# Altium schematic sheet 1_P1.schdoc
size 309 x 223 mm; Symbol: Sheet-Symbol_A4; Device: Sheet-Symbol_A4; @Project Name: Macro Pad; @Page Count: 1; @Update Date: 2024-09-08; @Create Date: 2024-01-24; @Schematic Name: Schematic1; @Page No: 1; @Page Name: P1; Company: t; Reviewed: EasyEDA; Version: V0.2; Page Size: A4; Part Number: JLCPCB-002; Drawn: Tiebe Groosman; @Board Name: Board1; @Create Time: 15:44:45; @Update Time: 14:38:24
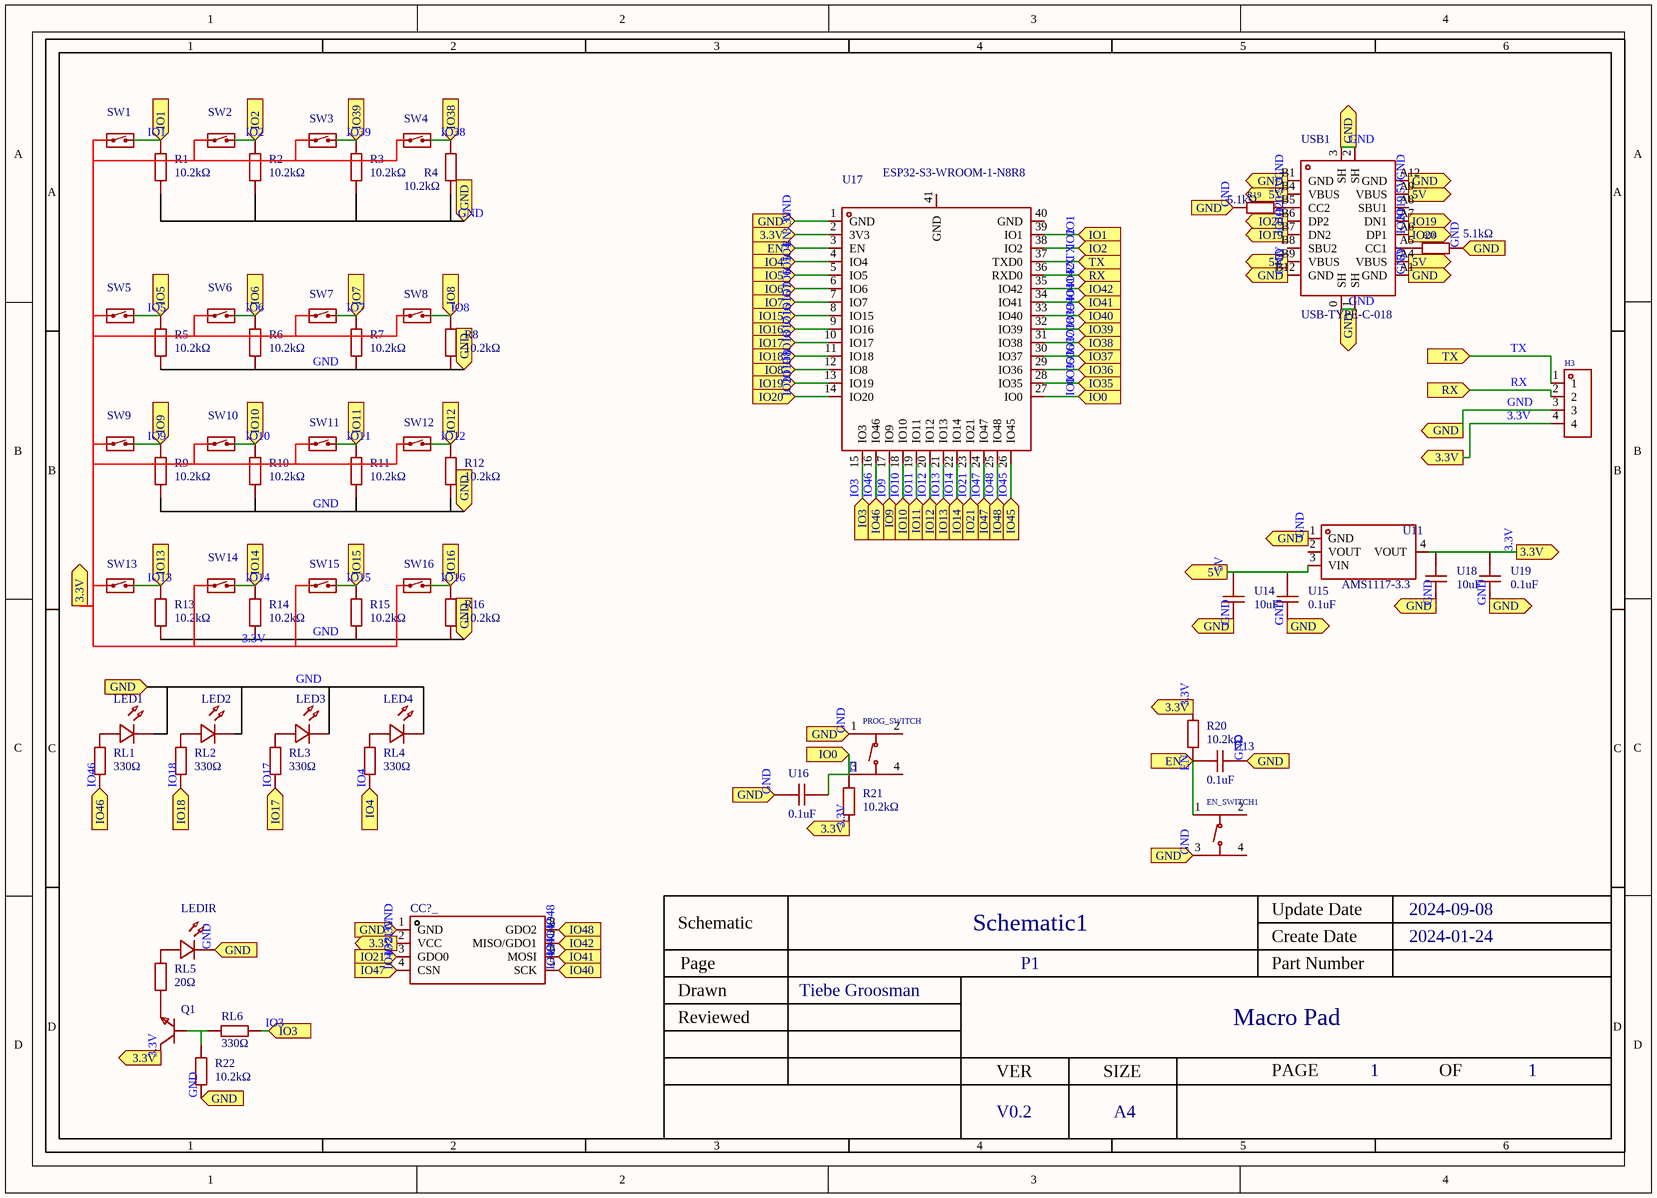
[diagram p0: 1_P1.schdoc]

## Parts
CC?_  CC1101 Module  [CC1101-BOARS]  (value not drawn)
EN_SWITCH1  TS-1187A-B-A-B  [SW-SMD_4P-L5.1-W5.1-P3.70-LS6.5-TL-2]  (value not drawn)
H3  HDR-M_2.54_1x4P  [HDR-TH_4P-P2.54-V-M]  (value not drawn)
LED1  LED_TH-R_5mm  [LED-TH_BD5.8-P2.54-FD]  (value not drawn)
LED2  LED_TH-R_5mm  [LED-TH_BD5.8-P2.54-FD]  (value not drawn)
LED3  LED_TH-R_5mm  [LED-TH_BD5.8-P2.54-FD]  (value not drawn)
LED4  LED_TH-R_5mm  [LED-TH_BD5.8-P2.54-FD]  (value not drawn)
LEDIR  LED_TH-R_5mm  [LED-TH_BD5.8-P2.54-FD]  (value not drawn)
PROG_SWITCH  TS-1187A-B-A-B  [SW-SMD_4P-L5.1-W5.1-P3.70-LS6.5-TL-2]  (value not drawn)
Q1  S8050_NPN  [SOT-23_L2.9-W1.3-P1.90-LS2.4-BR]  (value not drawn)
R1  10.2kΩ  [R1210]  (value not drawn)
R2  10.2kΩ  [R1210]  (value not drawn)
R3  10.2kΩ  [R1210]  (value not drawn)
R4  10.2kΩ  [R1210]  (value not drawn)
R5  10.2kΩ  [R1210]  (value not drawn)
R6  10.2kΩ  [R1210]  (value not drawn)
R7  10.2kΩ  [R1210]  (value not drawn)
R8  10.2kΩ  [R1210]  (value not drawn)
R9  10.2kΩ  [R1210]  (value not drawn)
R10  10.2kΩ  [R1210]  (value not drawn)
R11  10.2kΩ  [R1210]  (value not drawn)
R12  10.2kΩ  [R1210]  (value not drawn)
R13  10.2kΩ  [R1210]  (value not drawn)
R14  10.2kΩ  [R1210]  (value not drawn)
R15  10.2kΩ  [R1210]  (value not drawn)
R16  10.2kΩ  [R1210]  (value not drawn)
R18  5.1kΩ  [R1210]  (value not drawn)
R19  5.1kΩ  [R1210]  (value not drawn)
R20  10.2kΩ  [R1210]  (value not drawn)
R21  10.2kΩ  [R1210]  (value not drawn)
R22  10.2kΩ  [R1210]  (value not drawn)
RL1  330Ω  [R1210]  (value not drawn)
RL2  330Ω  [R1210]  (value not drawn)
RL3  330Ω  [R1210]  (value not drawn)
RL4  330Ω  [R1210]  (value not drawn)
RL5  20Ω  [R1210]  (value not drawn)
RL6  330Ω  [R1210]  (value not drawn)
SW1  CHERRY-MX-LED  [CHERRYMX]  (value not drawn)
SW2  CHERRY-MX-LED  [CHERRYMX]  (value not drawn)
SW3  CHERRY-MX-LED  [CHERRYMX]  (value not drawn)
SW4  CHERRY-MX-LED  [CHERRYMX]  (value not drawn)
SW5  CHERRY-MX-LED  [CHERRYMX]  (value not drawn)
SW6  CHERRY-MX-LED  [CHERRYMX]  (value not drawn)
SW7  CHERRY-MX-LED  [CHERRYMX]  (value not drawn)
SW8  CHERRY-MX-LED  [CHERRYMX]  (value not drawn)
SW9  CHERRY-MX-LED  [CHERRYMX]  (value not drawn)
SW10  CHERRY-MX-LED  [CHERRYMX]  (value not drawn)
SW11  CHERRY-MX-LED  [CHERRYMX]  (value not drawn)
SW12  CHERRY-MX-LED  [CHERRYMX]  (value not drawn)
SW13  CHERRY-MX-LED  [CHERRYMX]  (value not drawn)
SW14  CHERRY-MX-LED  [CHERRYMX]  (value not drawn)
SW15  CHERRY-MX-LED  [CHERRYMX]  (value not drawn)
SW16  CHERRY-MX-LED  [CHERRYMX]  (value not drawn)
U11  AMS1117-3.3  [SOT-223-3_L6.5-W3.4-P2.30-LS7.0-BR]  (value not drawn)
U13  0.1uF  [C1210]  (value not drawn)
U14  10uF  [C1210]  (value not drawn)
U15  0.1uF  [C1210]  (value not drawn)
U16  0.1uF  [C1210]  (value not drawn)
U17  ESP32-S3-WROOM-1-N8R8  [WIRELM-SMD_ESP32-S3-WROOM-1]  (value not drawn)
U18  10uF  [C1210]  (value not drawn)
U19  0.1uF  [C1210]  (value not drawn)
USB1  USB-TYPE-C-018  [USB-C_SMD-TYPE-C-31-M-12]  (value not drawn)

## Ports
3.3V (in), 3.3V (out), 5V (out), EN (in), GND (in), GND (out), IO0 (in), IO1 (in), IO2 (in), IO3 (in), IO4 (in), IO5 (in), IO6 (in), IO7 (in), IO8 (in), IO9 (in), IO10 (in), IO11 (in), IO12 (in), IO13 (in), IO14 (in), IO15 (in), IO16 (in), IO17 (in), IO18 (in), IO19 (in), IO19 (out), IO20 (in), IO20 (out), IO21 (in), IO35 (in), IO36 (in), IO37 (in), IO38 (in), IO39 (in), IO40 (in), IO41 (in), IO42 (in), IO45 (in), IO46 (in), IO47 (in), IO48 (in), RX (in), TX (in)

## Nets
3.3V: CC?_.2(VCC) H3.4 Q1.3(C) R20.2 R21.1 SW1.1 SW2.1 SW3.1 SW4.1 SW5.1 SW6.1 SW7.1 SW8.1 SW9.1 SW10.1 SW11.1 SW12.1 SW13.1 SW14.1 SW15.1 SW16.1 U11.4(VOUT) U17.2(3V3) U18.2 U19.2 ; port 3.3V
5V: U11.3(VIN) U14.2 U15.2 USB1.A4(VBUS) USB1.A9(VBUS) USB1.B4(VBUS) USB1.B9(VBUS) ; port 5V
[]: PROG_SWITCH.3(C) R21.2 U16.1 U17.27(IO0) ; port IO0  [also labelled IO0]
EN: EN_SWITCH1.1(A) R20.1 U13.1 U17.3(EN) ; port EN
GND: CC?_.1(GND) EN_SWITCH1.3(C) H3.3 LED1.2(A) LED2.2(A) LED3.2(A) LED4.2(A) LEDIR.2(A) PROG_SWITCH.1(A) R1.1 R2.1 R3.1 R4.1 R5.1 R6.1 R7.1 R8.1 R9.1 R10.1 R11.1 R12.1 R13.1 R14.1 R15.1 R16.1 R18.1 R19.1 R22.1 U11.1(GND) U13.2 U14.1 U15.1 U16.2 U17.1(GND) U18.1 U19.1 USB1.0(SH) USB1.1(SH) USB1.2(SH) USB1.3(SH) USB1.A1(GND) USB1.A12(GND) USB1.B1(GND) USB1.B12(GND) ; port GND
IO1: R1.2 SW1.2 U17.39(IO1) ; port IO1
IO2: R2.2 SW2.2 U17.38(IO2) ; port IO2
IO3: RL6.2 U17.15(IO3) ; port IO3
IO4: RL4.2 U17.4(IO4) ; port IO4
IO5: R5.2 SW5.2 U17.5(IO5) ; port IO5
IO6: R6.2 SW6.2 U17.6(IO6) ; port IO6
IO7: R7.2 SW7.2 U17.7(IO7) ; port IO7
IO8: R8.2 SW8.2 U17.12(IO8) ; port IO8
IO9: R9.2 SW9.2 U17.17(IO9) ; port IO9
IO10: R10.2 SW10.2 U17.18(IO10) ; port IO10
IO11: R11.2 SW11.2 U17.19(IO11) ; port IO11
IO12: R12.2 SW12.2 U17.20(IO12) ; port IO12
IO13: R13.2 SW13.2 U17.21(IO13) ; port IO13
IO14: R14.2 SW14.2 U17.22(IO14) ; port IO14
IO15: R15.2 SW15.2 U17.8(IO15) ; port IO15
IO16: R16.2 SW16.2 U17.9(IO16) ; port IO16
IO17: RL3.2 U17.10(IO17) ; port IO17
IO18: RL2.2 U17.11(IO18) ; port IO18
IO19: U17.13(IO19) USB1.A7(DN1) USB1.B7(DN2) ; port IO19
IO20: U17.14(IO20) USB1.A6(DP1) USB1.B6(DP2) ; port IO20
IO21: CC?_.3(GDO0) U17.23(IO21) ; port IO21
IO35: U17.28(IO35) ; port IO35
IO36: U17.29(IO36) ; port IO36
IO37: U17.30(IO37) ; port IO37
IO38: R4.2 SW4.2 U17.31(IO38) ; port IO38
IO39: R3.2 SW3.2 U17.32(IO39) ; port IO39
IO40: CC?_.5(SCK) U17.33(IO40) ; port IO40
IO41: CC?_.6(MOSI) U17.34(IO41) ; port IO41
IO42: CC?_.7(MISO/GDO1) U17.35(IO42) ; port IO42
IO45: U17.26(IO45) ; port IO45
IO46: RL1.2 U17.16(IO46) ; port IO46
IO47: CC?_.4(CSN) U17.24(IO47) ; port IO47
IO48: CC?_.8(GDO2) U17.25(IO48) ; port IO48
RX: H3.2 U17.36(RXD0) ; port RX
TX: H3.1 U17.37(TXD0) ; port TX
NetLED1_1: LED1.1(C) RL1.1
NetLED2_1: LED2.1(C) RL2.1
NetLED3_1: LED3.1(C) RL3.1
NetLED4_1: LED4.1(C) RL4.1
NetLEDIR_1: LEDIR.1(C) RL5.1
NetQ1_1: Q1.1(B) R22.2 RL6.1
NetQ1_2: Q1.2(E) RL5.2
NetR18_2: R18.2 USB1.A5(CC1)
NetR19_2: R19.2 USB1.B5(CC2)

Not connected (* = marked no-connect by the designer): EN_SWITCH1 2(B) 4(D); PROG_SWITCH 2(B) 4(D); U11 2(VOUT); U17 40(GND) 41(GND); USB1 A8(SBU1) B8(SBU2)

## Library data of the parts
CC?_ = CC1101 Module: Add into BOM: yes
EN_SWITCH1 PROG_SWITCH = TS-1187A-B-A-B: Circuit:SPST Actuator Style:Round Button Operating Force:160gf Mounting Style:Brick nogging Switch Length:5.1mm Switch Width:5.1mm Switch Height:1.5mm Strike Gundam:不带 Contact Current:50mA Voltage Rating (DC):12V Insulation Resistance:- Actuator/Cap Color; Manufacturer: XKB Connectivity(中国星坤); Add into BOM: yes; Circuit: SPST; Operating Force: 160gf; Switch Length: 5.1mm; Switch Height: 1.5mm; Strike Gundam: 不带; Contact Current: 50mA; Voltage Rating (DC): 12V; Actuator/Cap Color: 金色; With Lamp: No; Mechanical Life: 10万次
H3 = HDR-M_2.54_1x4P: Manufacturer: XFCN(兴飞); Symbol: PZ254V-11-04P; Convert to PCB: yes; Check: false
LED1-LED4 = LED_TH-R_5mm: Convert to PCB: yes; Check: false
LEDIR = LED_TH-R_5mm: Convert to PCB: yes
Q1 = S8050_NPN: Symbol: NPN; Add into BOM: yes
R1-R16 R20-R22 = 1210W2F1022T5E: Type:Thick Film Resistors Resistance:10200Ω Tolerance:±1% Tolerance:±1% Power(Watts): Overload Voltage (Max): Temperature Coefficient:±100ppm/℃ Temperature Coefficient:±100ppm/℃ Operating Temperature Range:-55℃~+155℃ Operating Temperature Range:-55℃~+155℃; Manufacturer: UNI-ROYAL(厚声); Symbol: 0402WGF1022TCE; Add into BOM: yes; Tolerance: ±1%
R18 R19 = SCR1210J5K1: Type:Thick Film Resistors Resistance: Tolerance:±5% Tolerance:±5% Power(Watts): Overload Voltage (Max): Operating Temperature Range:-55℃~+155℃ Operating Temperature Range:-55℃~+155℃; Manufacturer: VO(翔胜); Symbol: 0402WGJ0512TCE; Add into BOM: yes; Tolerance: ±5%; Temperature Coefficient: ±100ppm/℃
RL1-RL6 = RTT12331JTP: Type:Thick Film Resistors Resistance: Tolerance:±5% Tolerance:±5% Power(Watts): Overload Voltage (Max): Temperature Coefficient:±100ppm/℃ Temperature Coefficient:±100ppm/℃ Operating Temperature Range:-55℃~+155℃ Operating Temperature Range:-55℃~+155℃; Manufacturer: RALEC(旺诠); Symbol: 0402WGJ0331TCE; Add into BOM: yes; Tolerance: ±5%
SW1-SW16 = CHERRY-MX-LED: Manufacturer Part: Cherry MX Green; Manufacturer: Cherry; Add into BOM: yes
U11 = AMS1117-3.3_C6186: Output Type: Maximum Input Voltage:- Output Voltage:3.3V Output Voltage:3.3V MAX Output Current:1A Power Supply Rejection Ratio (PSRR):72dB@(120Hz) Dropout Voltage:1.3V@(800mA) standby current:- Noise:- Feature:- Operating Temperature:- Operating Temperat; Manufacturer: AMS; Add into BOM: yes; Output Voltage: 3.3V; MAX Output Current: 1A; Output Polarity: Positive electrode; Number of Outputs: 1
U13-U16 U18 U19 = CC1210KKX7R9BB105: Capacitance: Tolerance:±10% Tolerance:±10% Voltage Rated: Temperature Coefficient:; Manufacturer: YAGEO(国巨); Symbol: CGA0402X5R105K500GT; Add into BOM: yes; Tolerance: ±10%; Voltage Rated: 50V
U17 = ESP32-S3-WROOM-1-N8R8: Manufacturer: ESPRESSIF(乐鑫); Symbol: ESP32-S3-WROOM-1(N8R8); Add into BOM: yes
USB1 = USB-TYPE-C-018: Connector Type:Type-C Standard:- Gender:Female Mounting Style:卧贴 Number of Contacts:16P Number of Ports:1 Current Rating - Power (Max):3A Operating Temperature Range:-25℃~+85℃ Operating Temperature Range:-25℃~+85℃; Manufacturer: DEALON(德艺隆); Add into BOM: yes; Connector Type: Type-C; Gender: Female; Number of Ports: 1; Number of Contacts: 16P; Current Rating - Power (Max): 3A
